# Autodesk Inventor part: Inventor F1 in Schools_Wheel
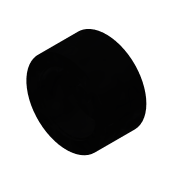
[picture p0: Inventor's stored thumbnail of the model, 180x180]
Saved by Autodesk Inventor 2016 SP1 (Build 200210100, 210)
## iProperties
Created: 2015-12
Part Number: Inventor F1 in Schools_Wheel
Material: Generic
Document SubType Name: Modeling
Designer: Autodesk Inc.
Density: 1 g/cm^3
Appearance: Black
Author: Autodesk Inc
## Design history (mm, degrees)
feature "Body1"
body "Solid1"
